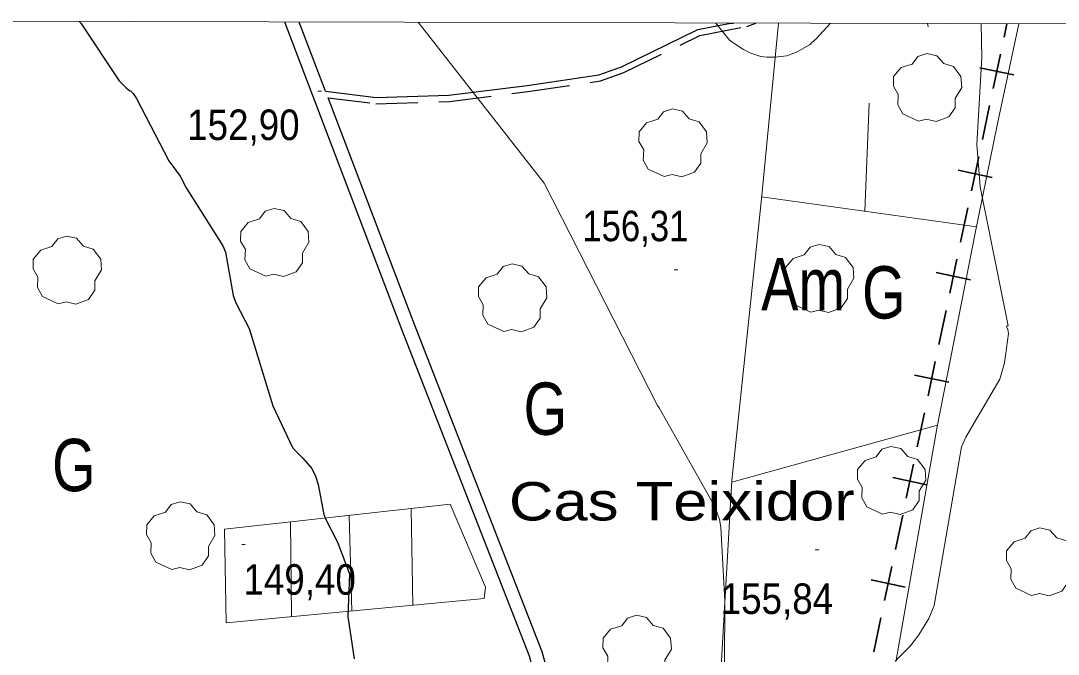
# Model space of a CAD drawing. Extents: x 480264 to 484872, y 4381275 to 4384491.
# Drawn here: x 480605 to 480902.2, y 4383962.9 to 4384144.4 of the extents above; entities that cross this region are included whole.
import ezdxf
from ezdxf.enums import TextEntityAlignment as Align

# ---------------------------------------------------------------- set-up
doc = ezdxf.new("R2010")
doc.units = 0
doc.header["$LTSCALE"] = 4
doc.linetypes.add('MEDIUM_DASHED', pattern=[4.5, 3, -1.5])
for name, color, linetype, lineweight in [('1', 7, 'Continuous', 13), ('29', 7, 'Continuous', 13), ('34', 7, 'Continuous', 35), ('38', 7, 'Continuous', 25), ('51', 7, 'Continuous', 13), ('7', 7, 'Continuous', 13), ('8', 7, 'Continuous', 25), ('9', 7, 'Continuous', 13)]:
    doc.layers.add(name, color=color, linetype=linetype, lineweight=lineweight)
doc.layers.add('31', color=7, linetype='Continuous')
doc.layers.add('5', color=7, linetype='Continuous')

msp = doc.modelspace()

# ---------------------------------------------------------------- linework, layer by layer
at = {"layer": '1'}
msp.add_lwpolyline([(480523.1, 4384144.4), (484100.5, 4384135.8), (484095.6, 4381823.6), (480517.1, 4381832.1)], close=True, dxfattribs=at)
at = {"layer": '29'}
for points in [[(480862.17, 4384115.59), (480857.63, 4384117.71), (480856.22, 4384120.25), (480856.32, 4384123.23), (480854.95, 4384125.64), (480854.99, 4384128.39), (480857.15, 4384130.99), (480860.34, 4384131.99), (480861.99, 4384134.18), (480864.56, 4384135.01), (480867.42, 4384134.36), (480869.37, 4384132.09), (480872.18, 4384131.27), (480874.31, 4384128.42), (480874.55, 4384125.29), (480872.67, 4384122.14), (480872.67, 4384119.46), (480870.85, 4384116.85), (480867.23, 4384115.51), (480864.46, 4384116.14)], [(480789.28, 4384099.74), (480784.74, 4384101.86), (480783.33, 4384104.4), (480783.43, 4384107.38), (480782.06, 4384109.79), (480782.1, 4384112.54), (480784.26, 4384115.14), (480787.45, 4384116.14), (480789.1, 4384118.33), (480791.67, 4384119.16), (480794.53, 4384118.51), (480796.48, 4384116.24), (480799.29, 4384115.42), (480801.42, 4384112.57), (480801.66, 4384109.44), (480799.78, 4384106.29), (480799.78, 4384103.61), (480797.96, 4384101), (480794.34, 4384099.66), (480791.57, 4384100.29)], [(480675.19, 4384071.21), (480670.65, 4384073.33), (480669.24, 4384075.87), (480669.34, 4384078.85), (480667.97, 4384081.26), (480668.01, 4384084.01), (480670.17, 4384086.61), (480673.36, 4384087.61), (480675.01, 4384089.8), (480677.58, 4384090.63), (480680.44, 4384089.98), (480682.39, 4384087.71), (480685.2, 4384086.89), (480687.33, 4384084.04), (480687.57, 4384080.91), (480685.69, 4384077.76), (480685.69, 4384075.08), (480683.87, 4384072.47), (480680.25, 4384071.13), (480677.48, 4384071.76)], [(480615.77, 4384063.29), (480611.23, 4384065.41), (480609.82, 4384067.95), (480609.92, 4384070.93), (480608.55, 4384073.34), (480608.59, 4384076.09), (480610.75, 4384078.69), (480613.94, 4384079.69), (480615.59, 4384081.88), (480618.16, 4384082.71), (480621.02, 4384082.06), (480622.97, 4384079.79), (480625.78, 4384078.97), (480627.91, 4384076.12), (480628.15, 4384072.99), (480626.27, 4384069.84), (480626.27, 4384067.16), (480624.45, 4384064.55), (480620.83, 4384063.21), (480618.06, 4384063.84)], [(480831.27, 4384060.9), (480826.73, 4384063.02), (480825.32, 4384065.56), (480825.42, 4384068.54), (480824.05, 4384070.95), (480824.09, 4384073.7), (480826.25, 4384076.3), (480829.44, 4384077.3), (480831.09, 4384079.49), (480833.66, 4384080.32), (480836.52, 4384079.67), (480838.47, 4384077.4), (480841.28, 4384076.58), (480843.41, 4384073.73), (480843.65, 4384070.6), (480841.77, 4384067.45), (480841.77, 4384064.77), (480839.95, 4384062.16), (480836.33, 4384060.82), (480833.56, 4384061.45)], [(480743.33, 4384055.35), (480738.79, 4384057.47), (480737.38, 4384060.01), (480737.48, 4384062.99), (480736.11, 4384065.4), (480736.15, 4384068.15), (480738.31, 4384070.75), (480741.5, 4384071.75), (480743.15, 4384073.94), (480745.72, 4384074.77), (480748.58, 4384074.12), (480750.53, 4384071.85), (480753.34, 4384071.03), (480755.47, 4384068.18), (480755.71, 4384065.05), (480753.83, 4384061.9), (480753.83, 4384059.22), (480752.01, 4384056.61), (480748.39, 4384055.27), (480745.62, 4384055.9)], [(480851.87, 4384003.04), (480847.33, 4384005.16), (480845.92, 4384007.7), (480846.02, 4384010.68), (480844.65, 4384013.09), (480844.69, 4384015.84), (480846.85, 4384018.44), (480850.04, 4384019.44), (480851.69, 4384021.63), (480854.26, 4384022.46), (480857.12, 4384021.81), (480859.07, 4384019.54), (480861.88, 4384018.72), (480864.01, 4384015.87), (480864.25, 4384012.74), (480862.37, 4384009.59), (480862.37, 4384006.91), (480860.55, 4384004.3), (480856.93, 4384002.96), (480854.16, 4384003.59)], [(480648.26, 4383987.19), (480643.72, 4383989.31), (480642.31, 4383991.85), (480642.41, 4383994.83), (480641.04, 4383997.24), (480641.08, 4383999.99), (480643.24, 4384002.59), (480646.43, 4384003.59), (480648.08, 4384005.78), (480650.65, 4384006.61), (480653.51, 4384005.96), (480655.46, 4384003.69), (480658.27, 4384002.87), (480660.4, 4384000.02), (480660.64, 4383996.89), (480658.76, 4383993.74), (480658.76, 4383991.06), (480656.94, 4383988.45), (480653.32, 4383987.11), (480650.55, 4383987.74)], [(480894.54, 4383979.72), (480890, 4383981.84), (480888.59, 4383984.38), (480888.69, 4383987.36), (480887.32, 4383989.77), (480887.36, 4383992.52), (480889.52, 4383995.12), (480892.71, 4383996.12), (480894.36, 4383998.31), (480896.93, 4383999.14), (480899.79, 4383998.49), (480901.74, 4383996.22), (480904.55, 4383995.4), (480906.68, 4383992.55), (480906.92, 4383989.42), (480905.04, 4383986.27), (480905.04, 4383983.59), (480903.22, 4383980.98), (480899.6, 4383979.64), (480896.83, 4383980.27)], [(480778.98, 4383954.69), (480774.44, 4383956.81), (480773.03, 4383959.35), (480773.13, 4383962.33), (480771.76, 4383964.74), (480771.8, 4383967.49), (480773.96, 4383970.09), (480777.15, 4383971.09), (480778.8, 4383973.28), (480781.37, 4383974.11), (480784.23, 4383973.46), (480786.18, 4383971.19), (480788.99, 4383970.37), (480791.12, 4383967.52), (480791.36, 4383964.39), (480789.48, 4383961.24), (480789.48, 4383958.56), (480787.66, 4383955.95), (480784.04, 4383954.61), (480781.27, 4383955.24)]]:
    msp.add_lwpolyline(points, close=True, dxfattribs=at)
at = {"layer": '34'}
for p, q in [((480887.47, 4384143.52), (480886.66, 4384139.68)), ((480885.62, 4384134.79), (480883.55, 4384125.01)), ((480879.69, 4384130.93), (480889.48, 4384128.86)), ((480882.51, 4384120.11), (480880.43, 4384110.33)), ((480879.4, 4384105.44), (480877.32, 4384095.66)), ((480873.47, 4384101.59), (480883.25, 4384099.51)), ((480876.28, 4384090.77), (480874.21, 4384080.99)), ((480873.17, 4384076.09), (480871.1, 4384066.31)), ((480867.24, 4384072.24), (480877.03, 4384070.17)), ((480870.06, 4384061.42), (480867.98, 4384051.64)), ((480866.95, 4384046.75), (480864.87, 4384036.96)), ((480861.02, 4384042.89), (480870.8, 4384040.82)), ((480863.83, 4384032.07), (480861.76, 4384022.29)), ((480860.72, 4384017.4), (480858.65, 4384007.62)), ((480854.79, 4384013.55), (480864.57, 4384011.47)), ((480857.61, 4384002.73), (480855.53, 4383992.94)), ((480854.5, 4383988.05), (480852.42, 4383978.27)), ((480848.57, 4383984.2), (480858.35, 4383982.12)), ((480851.38, 4383973.38), (480849.31, 4383963.6))]:
    msp.add_line(p, q, dxfattribs=at)
at = {"layer": '38'}
msp.add_line((480692.32, 4384124.19), (480684.76, 4384144.01), dxfattribs=at)
for points in [[(480522.56, 4383936.97), (480733.12, 4383945.95), (480746.43, 4383946.75), (480749.64, 4383947.65), (480751.85, 4383949.62), (480752.57, 4383952.77), (480752.47, 4383955.89), (480750.69, 4383962.33), (480714.17, 4384055.97), (480680.61, 4384144.02)], [(480692.32, 4384124.19), (480706.81, 4384122.42), (480727.67, 4384123.06), (480750.03, 4384125.86), (480770.6, 4384128.91), (480777.04, 4384131.21), (480798.92, 4384141.88), (480808.32, 4384143.71), (480808.34, 4384143.71), (480808.36, 4384143.71), (480808.38, 4384143.71), (480808.4, 4384143.71), (480808.42, 4384143.71), (480808.44, 4384143.71), (480808.46, 4384143.71), (480808.48, 4384143.71), (480808.5, 4384143.71), (480808.52, 4384143.71), (480808.54, 4384143.71), (480808.56, 4384143.71), (480808.58, 4384143.71), (480808.6, 4384143.71), (480808.62, 4384143.71), (480808.64, 4384143.71), (480808.66, 4384143.71), (480808.68, 4384143.71), (480808.7, 4384143.71), (480808.72, 4384143.71), (480808.74, 4384143.71), (480808.76, 4384143.71), (480808.77, 4384143.71), (480808.78, 4384143.71), (480808.79, 4384143.71), (480808.8, 4384143.71), (480808.81, 4384143.71), (480808.82, 4384143.71), (480808.83, 4384143.71), (480808.84, 4384143.71), (480808.85, 4384143.71), (480808.86, 4384143.71)], [(480808.86, 4384143.71), (480808.87, 4384143.71), (480808.88, 4384143.71), (480808.89, 4384143.71), (480808.9, 4384143.71), (480808.91, 4384143.71), (480808.92, 4384143.71), (480808.93, 4384143.71), (480808.94, 4384143.71), (480808.95, 4384143.71), (480808.96, 4384143.71), (480808.97, 4384143.71), (480808.98, 4384143.71), (480808.99, 4384143.71), (480809, 4384143.71), (480809.01, 4384143.71), (480809.02, 4384143.71), (480809.03, 4384143.71), (480809.04, 4384143.71), (480809.05, 4384143.71), (480809.06, 4384143.71), (480809.07, 4384143.71), (480809.08, 4384143.71), (480809.09, 4384143.71), (480809.1, 4384143.71), (480809.11, 4384143.71)], [(480522.55, 4383933.08), (480642.54, 4383938.48), (480733.32, 4383942.07), (480747.08, 4383942.91), (480751.56, 4383944.15), (480755.36, 4383947.56), (480756.46, 4383952.39), (480756.33, 4383956.48), (480754.37, 4383963.56), (480717.79, 4384057.37), (480693.05, 4384122.28)]]:
    msp.add_lwpolyline(points, dxfattribs=at)
at = {"layer": '38', "linetype": 'MEDIUM_DASHED'}
msp.add_lwpolyline([(480693.05, 4384122.28), (480706.73, 4384120.61), (480727.81, 4384121.25), (480750.27, 4384124.07), (480771.04, 4384127.15), (480777.75, 4384129.54), (480799.5, 4384140.15), (480812.93, 4384142.77), (480815.56, 4384143.7)], dxfattribs=at)
at = {"layer": '51'}
for p, q in [((480864.93, 4384142.67), (480864.72, 4384143.58)), ((480847.97, 4384120.74), (480846.81, 4384089.81)), ((480878.71, 4384085.31), (480817.22, 4384093.98)), ((480808.7, 4384012.24), (480867.54, 4384028.51)), ((480716.85, 4384004.65), (480717.36, 4383976.97)), ((480682.28, 4384000.85), (480682.6, 4383973.68)), ((480699.83, 4383975.31), (480699.12, 4384002.7))]:
    msp.add_line(p, q, dxfattribs=at)
for points in [[(480819.7, 4383897.23), (480802.34, 4383900.24), (480805.05, 4383949.41), (480808.72, 4384012.66), (480817.16, 4384093.4), (480822.07, 4384143.68)], [(480890.88, 4384143.52), (480884.7, 4384114.51), (480878.44, 4384084.04), (480867.35, 4384027.57), (480854.79, 4383955.8), (480842.5, 4383892.71)]]:
    msp.add_lwpolyline(points, dxfattribs=at)
msp.add_lwpolyline([(480663.4, 4383998.76), (480663.82, 4383971.91), (480737.72, 4383978.89), (480738.09, 4383982.14), (480727.99, 4384005.87)], close=True, dxfattribs=at)
at = {"layer": '7'}
for p, q in [((480690.13, 4384124.2), (480691.13, 4384124.2)), ((480792.2, 4384073.07), (480793.2, 4384073.07)), ((480668.29, 4383994.33), (480669.29, 4383994.33)), ((480832.57, 4383992.78), (480833.57, 4383992.78))]:
    msp.add_line(p, q, dxfattribs=at)
at = {"layer": '8'}
msp.add_lwpolyline([(480621.79, 4384144.16), (480622.26, 4384143.68), (480633.21, 4384127.19), (480635.19, 4384125.13), (480635.89, 4384124.6), (480636.38, 4384124.3), (480636.52, 4384124.19), (480637.22, 4384123.53), (480638.17, 4384122.11), (480647.39, 4384104.25), (480650.68, 4384099.86), (480652.35, 4384096.56), (480662.92, 4384079.94), (480663.68, 4384078.09), (480665.86, 4384065.64), (480666.64, 4384063.54), (480670.47, 4384056.24), (480677.22, 4384034.03), (480682.88, 4384022.14), (480683.58, 4384021.23), (480685.78, 4384019.06), (480688.34, 4384016.08), (480689.43, 4384013.89), (480690.22, 4384011.57), (480691.86, 4384002.92), (480692.32, 4384001.72), (480695.76, 4383995.06), (480699.15, 4383985.93), (480698.69, 4383973.73), (480700.5, 4383961.63)], dxfattribs=at)
at = {"layer": '9'}
for points in [[(480806.54, 4383960.04), (480806.69, 4383978.14), (480805.49, 4383999.36), (480805.16, 4384001.53), (480803.9, 4384005.06), (480787.87, 4384033.51), (480787.39, 4384034.14), (480754.94, 4384097.89), (480718.87, 4384143.93)], [(480804.06, 4384143.72), (480808.09, 4384138.74), (480811.98, 4384136.13), (480814.08, 4384135.08), (480816.99, 4384134.18), (480818.71, 4384133.91), (480820.97, 4384133.9), (480824.39, 4384134.35), (480827.38, 4384135.47), (480830.93, 4384137.45), (480831.19, 4384137.65), (480831.43, 4384137.92), (480832.8, 4384139.17), (480836.96, 4384143.65)], [(480880.13, 4384143.54), (480880.32, 4384133.84), (480878.86, 4384108.97), (480879.83, 4384096.78), (480887.81, 4384056.98), (480887.51, 4384056.96), (480887.36, 4384056.89), (480887.34, 4384056.84), (480887.34, 4384056.79), (480887.44, 4384056.51), (480887.65, 4384056.13), (480887.71, 4384056.06), (480887.75, 4384056)], [(480887.75, 4384056), (480887.87, 4384055.28), (480887.9, 4384054.86), (480887.91, 4384054.82), (480886.76, 4384046.41), (480885.42, 4384041.73), (480875.71, 4384025.08), (480874.45, 4384022.31), (480866.62, 4383976.9), (480865.1, 4383973.11), (480862.23, 4383968.43), (480859.73, 4383965.26), (480855.54, 4383960.99)]]:
    msp.add_lwpolyline(points, dxfattribs=at)

# ---------------------------------------------------------------- texts
at = {"layer": '31', "width": 0.8}
for s, p in [('Am', (480829.105, 4384061.38)), ('G', (480852.22, 4384059.07)), ('G', (480755.27, 4384025.75)), ('G', (480620.23, 4384009.61))]:
    msp.add_text(s, height=15, dxfattribs=at).set_placement(p, align=Align.CENTER)
at = {"layer": '5', "width": 1.2}
msp.add_text('Cas Teixidor', height=11, dxfattribs=at).set_placement((480744.84, 4384001.23))
at = {"layer": '7'}
for s, width, p in [('152,90', 0.9, (480652.68, 4384110.2)), ('156,31', 0.85, (480765.84, 4384081.23)), ('149,40', 0.9, (480668.79, 4383979.96)), ('155,84', 0.9, (480805.49, 4383974.45))]:
    msp.add_text(s, height=8.75, dxfattribs=dict(at, width=width)).set_placement(p)

doc.saveas('drawing.dxf')
